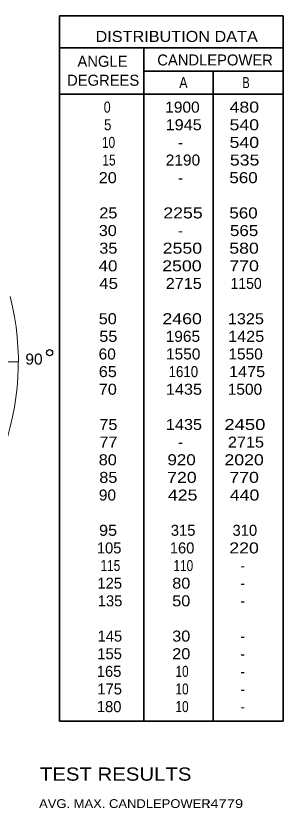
# Model space of a CAD drawing. Extents: x -39.6 to 16.1, y -17.6 to 34.
# Drawn here: x 12.27 to 15.3, y 25.05 to 34.03 of the extents above; entities that cross this region are included whole.
import ezdxf
from ezdxf.enums import TextEntityAlignment as Align

# ---------------------------------------------------------------- set-up
doc = ezdxf.new("R2010")
doc.units = 0
doc.header["$LTSCALE"] = 0.05
doc.layers.add('1', color=7, linetype='Continuous', lineweight=13)

msp = doc.modelspace()

# ---------------------------------------------------------------- linework, layer by layer
at = {"layer": '1', "lineweight": 35}
for p, q in [((12.77079, 34.03442), (15.30379, 34.03442)), ((12.77079, 34.03442), (12.77079, 26.03542)), ((15.30379, 34.03442), (15.30379, 26.03542)), ((12.77079, 33.67042), (15.30379, 33.67042)), ((13.72379, 33.67042), (13.72379, 26.03542)), ((13.72379, 33.40642), (15.30379, 33.40642)), ((14.51179, 33.40642), (14.51179, 26.03542)), ((12.77079, 33.14642), (15.30379, 33.14642)), ((12.77079, 26.03542), (15.30379, 26.03542))]:
    msp.add_line(p, q, dxfattribs=at)
at = {"layer": '1'}
for p, q in [((6.26879, 30.11042), (12.30279, 30.11042)), ((9.28579, 30.11042), (12.30379, 30.11142))]:
    msp.add_line(p, q, dxfattribs=at)
at = {"layer": '1', "lineweight": 25}
msp.add_circle((12.65679, 30.21442), 0.03489, dxfattribs=at)
at = {"layer": '1'}
msp.add_arc((9.28579, 30.11042), 3.01743, 165.81631, 14.18369, dxfattribs=at)

# ---------------------------------------------------------------- texts
for s, height, width, p in [('DISTRIBUTION DATA', 0.125, 1.1, (14.09729, 33.73842)), ('A', 0.125, 0.85, (14.17379, 33.21442)), ('B', 0.125, 0.75, (14.88329, 33.21442)), ('0', 0.125, 0.85, (13.30979, 32.93642)), ('1900', 0.125, 1.05, (14.16279, 32.93642)), ('480', 0.125, 1.2, (14.86379, 32.93642)), ('5', 0.125, 0.9, (13.31629, 32.73642)), ('1945', 0.125, 1.1, (14.17679, 32.73642)), ('540', 0.125, 1.2, (14.86379, 32.73642)), ('10', 0.125, 0.8, (13.32529, 32.53642)), ('540', 0.125, 1.2, (14.86379, 32.53642)), ('15', 0.125, 0.8, (13.33079, 32.33642)), ('2190', 0.125, 1.05, (14.16829, 32.33642)), ('535', 0.125, 1.2, (14.86729, 32.33642)), ('20', 0.125, 1.1, (13.31629, 32.13642)), ('560', 0.125, 1.15, (14.85479, 32.13642)), ('25', 0.125, 1.1, (13.32279, 31.73642)), ('2255', 0.125, 1.2, (14.16879, 31.73642)), ('560', 0.125, 1.15, (14.85479, 31.73642)), ('30', 0.125, 1.1, (13.31629, 31.53642)), ('565', 0.125, 1.15, (14.86129, 31.53642)), ('35', 0.125, 1.1, (13.32279, 31.33642)), ('2550', 0.125, 1.2, (14.16229, 31.33642)), ('580', 0.125, 1.2, (14.86079, 31.33642)), ('40', 0.125, 1.15, (13.31929, 31.13642)), ('2500', 0.125, 1.2, (14.15679, 31.13642)), ('770', 0.125, 1.2, (14.86179, 31.13642)), ('45', 0.125, 1.15, (13.32579, 30.93642)), ('2715', 0.125, 1.1, (14.17729, 30.93642)), ('1150', 0.125, 0.95, (14.88429, 30.93642)), ('50', 0.125, 1.1, (13.31629, 30.53642)), ('2460', 0.125, 1.2, (14.15929, 30.53642)), ('1325', 0.125, 1.1, (14.88179, 30.53642)), ('55', 0.125, 1.1, (13.32279, 30.33642)), ('1965', 0.125, 1.05, (14.16779, 30.33642)), ('1425', 0.125, 1.1, (14.88479, 30.33642)), ('90', 0.125, 1.05, (12.48029, 30.07842)), ('60', 0.125, 1.05, (13.31029, 30.13642)), ('1550', 0.125, 1.05, (14.17129, 30.13642)), ('1550', 0.125, 1.05, (14.87829, 30.13642)), ('65', 0.125, 1.1, (13.31679, 29.93642)), ('1610', 0.125, 0.9, (14.17329, 29.93642)), ('1475', 0.125, 1.1, (14.89529, 29.93642)), ('70', 0.125, 1.1, (13.31679, 29.73642)), ('1435', 0.125, 1.1, (14.17979, 29.73642)), ('1500', 0.125, 1.05, (14.87079, 29.73642)), ('75', 0.125, 1.1, (13.32329, 29.33642)), ('1435', 0.125, 1.1, (14.17979, 29.33642)), ('2450', 0.125, 1.25, (14.87029, 29.33642)), ('77', 0.125, 1.1, (13.32379, 29.13642)), ('2715', 0.125, 1.1, (14.88229, 29.13642)), ('80', 0.125, 1.1, (13.31629, 28.93642)), ('920', 0.125, 1.15, (14.15279, 28.93642)), ('2020', 0.125, 1.2, (14.86179, 28.93642)), ('85', 0.125, 1.1, (13.32279, 28.73642)), ('720', 0.125, 1.2, (14.15629, 28.73642)), ('770', 0.125, 1.2, (14.86179, 28.73642)), ('90', 0.125, 1.05, (13.31329, 28.53642)), ('425', 0.125, 1.2, (14.16529, 28.53642)), ('440', 0.125, 1.2, (14.86679, 28.53642)), ('95', 0.125, 1.1, (13.31979, 28.13642)), ('220', 0.125, 1.2, (14.86079, 27.93642)), ('115', 0.125, 0.8, (13.34629, 27.73642)), ('110', 0.125, 0.8, (14.17279, 27.73642)), ('80', 0.125, 1.1, (14.14929, 27.53642)), ('50', 0.125, 1.1, (14.14929, 27.33642)), ('30', 0.125, 1.1, (14.14929, 26.93642)), ('20', 0.125, 1.1, (14.14929, 26.73642)), ('10', 0.125, 0.8, (14.15829, 26.53642)), ('10', 0.125, 0.8, (14.15829, 26.33642)), ('10', 0.125, 0.8, (14.15829, 26.13642)), ('TEST RESULTS', 0.15, 1.15, (13.40579, 25.35842))]:
    msp.add_text(s, height=height, dxfattribs=dict(at, width=width)).set_placement(p, align=Align.CENTER)
for s, p in [('ANGLE', (13.25629, 33.45642)), ('CANDLEPOWER', (14.53229, 33.47142)), ('DEGREES', (13.26429, 33.24142)), ('-', (14.14029, 32.53642)), ('-', (14.14029, 32.13642)), ('-', (14.14029, 31.53642)), ('-', (14.14029, 29.13642)), ('315', (14.17029, 28.13642)), ('310', (14.86979, 28.13642)), ('105', (13.33179, 27.93642)), ('160', (14.15879, 27.93642)), ('-', (14.84529, 27.73642)), ('125', (13.33829, 27.53642)), ('-', (14.84529, 27.53642)), ('135', (13.34229, 27.33642)), ('-', (14.84529, 27.33642)), ('145', (13.34029, 26.93642)), ('-', (14.84529, 26.93642)), ('155', (13.33729, 26.73642)), ('-', (14.84529, 26.73642)), ('165', (13.33129, 26.53642)), ('-', (14.84529, 26.53642)), ('175', (13.33779, 26.33642)), ('-', (14.84529, 26.33642)), ('180', (13.33179, 26.13642)), ('-', (14.84529, 26.13642))]:
    msp.add_text(s, height=0.125, dxfattribs=at).set_placement(p, align=Align.CENTER)
for s, width, p in [('AVG. MAX. CANDLEPOWER', 1.1, (12.53779, 25.04842)), (':4779', 1.25, (14.43279, 25.04842))]:
    msp.add_text(s, height=0.1, dxfattribs=dict(at, width=width)).set_placement(p)

doc.saveas('drawing.dxf')
